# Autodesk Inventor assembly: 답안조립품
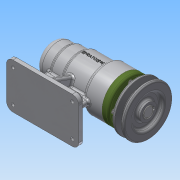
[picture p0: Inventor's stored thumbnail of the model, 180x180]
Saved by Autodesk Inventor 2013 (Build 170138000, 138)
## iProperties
Created: 2016-06
Part Number: 답안조립품
Document SubType Name: Assembly
Designer: Administrator
Author: Administrator
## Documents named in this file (12)
- C:\Users\Administrator\Desktop\460608V1025\답안조립품.iam
- C:\Users\Administrator\Desktop\460608V1025\V벨트풀리.ipt
- C:\Users\Administrator\Desktop\460608V1025\멈춤나사 M3x8.ipt
- C:\Users\Administrator\Desktop\460608V1025\베어링 6004.ipt
- C:\Users\Administrator\Desktop\460608V1025\베어링 51202.ipt
- C:\Users\Administrator\Desktop\460608V1025\본체.ipt
- C:\Users\Administrator\Desktop\460608V1025\볼트 M4 x 12.ipt
- C:\Users\Administrator\Desktop\460608V1025\어댑터슬리브.ipt
- C:\Users\Administrator\Desktop\460608V1025\오일 실.ipt
- C:\Users\Administrator\Desktop\460608V1025\축.ipt
- C:\Users\Administrator\Desktop\460608V1025\커버.ipt
- C:\Users\Administrator\Desktop\460608V1025\키 5 x 5 x 16.ipt
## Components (6 placed, 2 different names)
1. V벨트풀리:1 — 플러쉬:1
2. ISO 4762 M4 x 12:1
3. ISO 4762 M4 x 12:2
4. ISO 4762 M4 x 12:3
5. ISO 4762 M4 x 12:4
6. ISO 4762 M4 x 12:5
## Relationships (1: Flush 1)
- 플러쉬:1 [Flush]: V벨트풀리:1
